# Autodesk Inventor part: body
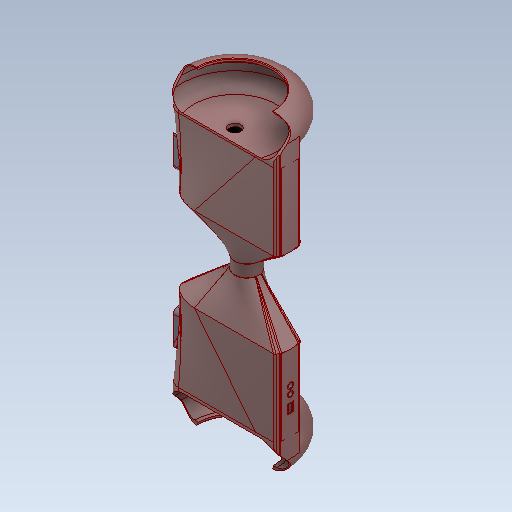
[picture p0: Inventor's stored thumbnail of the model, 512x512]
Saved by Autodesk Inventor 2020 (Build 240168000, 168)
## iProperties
Created: 2017-04
Part Number: body
Material: Générique
Document SubType Name: Modeling
Designer: bruno
Density: 1 g/cm^3
Appearance: Par défaut
Author: bruno
Sending System: SolidWorks 2016
Last Author: Samartha
Last Saved: 2017-04-03
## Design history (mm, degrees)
feature "Cut-Extrude11"
node "Solide1"
